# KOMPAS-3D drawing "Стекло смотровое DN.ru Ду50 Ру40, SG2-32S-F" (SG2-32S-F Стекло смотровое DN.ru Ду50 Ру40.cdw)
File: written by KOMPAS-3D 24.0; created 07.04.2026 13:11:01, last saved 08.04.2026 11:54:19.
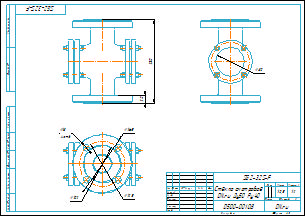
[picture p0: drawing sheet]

Document properties: Автор: Main; Форматы листов документа: A4; Полное имя файла: SG2-32S-F Стекло смотровое DN.ru Ду50 Ру40.m3d; Масса: 10.5; Наименование: Стекло смотровое DN.ru Ду50 Ру40; Количество листов документа: 1; Примечание: D500-00108

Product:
- Body: Тело 1  | qty 1
    Масса: 11.518228
- Part/product: Стекло смотровое DN.ru Ду50 Ру40  | designation SG2-32S-F
    Масса: 10.5
    Раздел спецификации: Прочие изделия
    Форматы листов документа: A4
    Примечание: D500-00108

Views: Вид 1, Снизу, Проекционный вид 2
Referenced files in D:\DN.ru Аутсерс\Стекло смотровое DN.ru\Стекло смотровое DN.ru SG2-34G-F тип В ГОСТ 21836-2021 Ду100 Ру16, углеродистая сталь, фланцевое\: SG2-34G-F тип В Стекло смотровое DN.ru Ду100 Ру16.m3d, SG2-34G-F тип ВСтекло смотровое DN.ru Ду100 Ру16.cdw
Referenced files in D:\DN.ru Аутсерс\Стекло смотровое DN.ru\SG2-32S-F Стекло смотровое DN.ru Ду50 Ру40\: SG2-32S-F Стекло смотровое DN.ru Ду50 Ру40.m3d
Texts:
  SG2-32S-F
  Стекло смотровое
  DN.ru Ду50 Ру40
  Стекло смотровое DN.ru Ду50 Ру40
  SG2-32S-F Стекло смотровое DN.ru Ду50 Ру40
Dimensions and other numbers on the sheet: 0; 3; 2; 4; 230; 20; 18; 4 отв.; 165; 102; 125; 1:2; 1; 10,5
